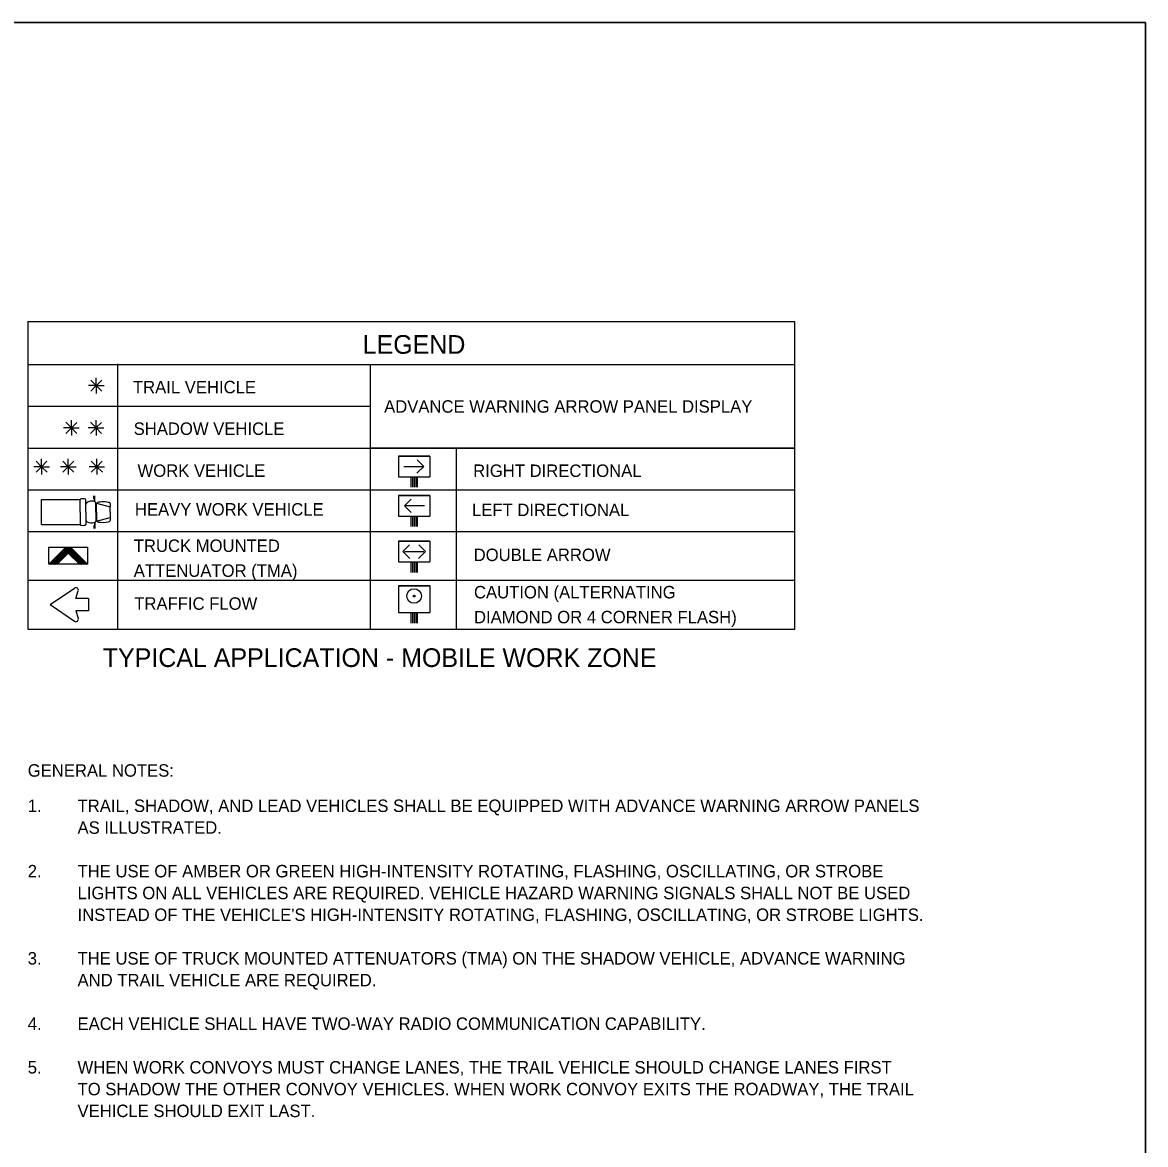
# Model space of a CAD drawing. Extents: x 1374027 to 1374537, y 380415 to 381405.
# Drawn here: x 1374143 to 1374197.1, y 381351.1 to 381405.2 of the extents above; entities that cross this region are included whole.
import ezdxf

# ---------------------------------------------------------------- set-up
doc = ezdxf.new("R2010")
doc.units = 0
doc.layers.add('DSN_DRFT_Junk-No-Plot', color=7, linetype='Continuous')
doc.layers.add('Working Level 1', color=7, linetype='Continuous')

msp = doc.modelspace()

# ---------------------------------------------------------------- linework, layer by layer
at = {"layer": 'DSN_DRFT_Junk-No-Plot'}
for points in [[(1374027.083, 381405.174), (1374197.083, 381405.174), (1374197.083, 381295.174), (1374027.083, 381295.174)], [(1374027.083, 381405.174), (1374027.083, 381295.174), (1374197.083, 381295.174), (1374197.083, 381405.174)]]:
    msp.add_lwpolyline(points, close=True, dxfattribs=at)
at = {"layer": 'Working Level 1'}
for p, q in [((1374143.22, 381390.771), (1374143.22, 381375.949)), ((1374143.22, 381390.771), (1374180.187, 381390.771)), ((1374180.187, 381375.949), (1374180.187, 381390.771)), ((1374143.22, 381388.69), (1374180.187, 381388.69)), ((1374147.548, 381388.725), (1374147.548, 381375.949)), ((1374147.548, 381388.725), (1374147.548, 381375.949)), ((1374159.725, 381388.69), (1374159.725, 381375.949)), ((1374146.527, 381387.675), (1374146.261, 381387.941)), ((1374146.52, 381387.67), (1374146.787, 381387.936)), ((1374146.527, 381387.675), (1374146.527, 381388.052)), ((1374146.527, 381387.675), (1374146.15, 381387.675)), ((1374146.527, 381387.675), (1374146.261, 381387.409)), ((1374146.527, 381387.675), (1374146.793, 381387.409)), ((1374146.527, 381387.675), (1374146.527, 381387.299)), ((1374146.527, 381387.675), (1374146.903, 381387.675)), ((1374143.22, 381386.679), (1374159.725, 381386.679)), ((1374145.329, 381385.642), (1374144.953, 381385.643)), ((1374145.329, 381385.642), (1374145.063, 381385.908)), ((1374145.329, 381385.642), (1374145.063, 381385.376)), ((1374145.323, 381385.637), (1374145.59, 381385.903)), ((1374145.329, 381385.642), (1374145.329, 381386.019)), ((1374145.329, 381385.642), (1374145.595, 381385.376)), ((1374145.329, 381385.642), (1374145.329, 381385.266)), ((1374145.329, 381385.642), (1374145.705, 381385.642)), ((1374146.512, 381385.642), (1374146.136, 381385.642)), ((1374146.512, 381385.642), (1374146.246, 381385.908)), ((1374146.512, 381385.642), (1374146.246, 381385.376)), ((1374146.507, 381385.637), (1374146.773, 381385.903)), ((1374146.512, 381385.642), (1374146.512, 381386.019)), ((1374146.512, 381385.642), (1374146.778, 381385.376)), ((1374146.512, 381385.642), (1374146.512, 381385.266)), ((1374146.512, 381385.642), (1374146.888, 381385.642)), ((1374143.22, 381384.668), (1374180.187, 381384.668)), ((1374180.187, 381384.668), (1374159.725, 381384.668)), ((1374163.861, 381384.668), (1374163.861, 381375.948)), ((1374143.888, 381383.769), (1374143.622, 381384.035)), ((1374143.883, 381383.763), (1374144.149, 381384.029)), ((1374143.888, 381383.769), (1374143.888, 381384.145)), ((1374145.178, 381383.769), (1374144.911, 381384.035)), ((1374145.172, 381383.763), (1374145.438, 381384.029)), ((1374145.178, 381383.769), (1374145.178, 381384.145)), ((1374146.551, 381383.769), (1374146.285, 381384.035)), ((1374146.546, 381383.763), (1374146.812, 381384.029)), ((1374146.551, 381383.769), (1374146.551, 381384.145)), ((1374161.088, 381384.279), (1374161.088, 381383.284)), ((1374162.593, 381384.279), (1374161.088, 381384.279)), ((1374161.088, 381384.279), (1374162.592, 381384.279)), ((1374162.305, 381383.782), (1374161.986, 381384.101)), ((1374162.593, 381384.279), (1374162.593, 381383.284)), ((1374143.888, 381383.769), (1374143.512, 381383.769)), ((1374143.888, 381383.769), (1374143.622, 381383.503)), ((1374143.888, 381383.769), (1374144.154, 381383.503)), ((1374143.888, 381383.769), (1374143.888, 381383.392)), ((1374143.888, 381383.769), (1374144.265, 381383.769)), ((1374145.178, 381383.769), (1374144.801, 381383.769)), ((1374145.178, 381383.769), (1374144.911, 381383.503)), ((1374145.178, 381383.769), (1374145.443, 381383.503)), ((1374145.178, 381383.769), (1374145.178, 381383.392)), ((1374145.178, 381383.769), (1374145.554, 381383.769)), ((1374146.551, 381383.769), (1374146.175, 381383.769)), ((1374146.551, 381383.769), (1374146.285, 381383.503)), ((1374146.551, 381383.769), (1374146.818, 381383.503)), ((1374146.551, 381383.769), (1374146.551, 381383.392)), ((1374146.551, 381383.769), (1374146.927, 381383.769)), ((1374161.342, 381383.782), (1374162.305, 381383.782)), ((1374162.305, 381383.782), (1374161.978, 381383.454)), ((1374161.088, 381383.284), (1374162.593, 381383.284)), ((1374161.689, 381383.284), (1374161.689, 381382.777)), ((1374161.764, 381383.284), (1374161.764, 381382.777)), ((1374161.84, 381383.284), (1374161.84, 381382.777)), ((1374161.915, 381383.284), (1374161.915, 381382.777)), ((1374161.991, 381383.284), (1374161.991, 381382.777)), ((1374143.22, 381382.658), (1374180.187, 381382.658)), ((1374143.22, 381382.658), (1374159.717, 381382.658)), ((1374143.888, 381382.182), (1374145.743, 381382.182)), ((1374143.888, 381380.982), (1374143.888, 381382.182)), ((1374145.743, 381381.582), (1374145.743, 381382.182)), ((1374146.027, 381381.582), (1374146.027, 381382.182)), ((1374146.41, 381382.217), (1374146.41, 381382.363)), ((1374146.434, 381382.076), (1374146.434, 381382.363)), ((1374146.453, 381382.076), (1374146.453, 381382.363)), ((1374146.504, 381381.582), (1374146.504, 381382.013)), ((1374146.543, 381382.013), (1374147.192, 381381.837)), ((1374146.543, 381381.582), (1374146.543, 381382.013)), ((1374161.088, 381382.385), (1374161.088, 381381.39)), ((1374162.593, 381382.385), (1374161.088, 381382.385)), ((1374161.088, 381382.385), (1374162.592, 381382.385)), ((1374161.374, 381381.888), (1374161.694, 381382.207)), ((1374162.337, 381381.888), (1374161.374, 381381.888)), ((1374161.374, 381381.888), (1374161.702, 381381.56)), ((1374162.593, 381382.385), (1374162.593, 381381.39)), ((1374145.743, 381381.582), (1374145.743, 381380.982)), ((1374146.027, 381381.582), (1374146.027, 381380.982)), ((1374146.504, 381381.582), (1374146.504, 381381.15)), ((1374146.543, 381381.582), (1374146.543, 381381.15)), ((1374146.543, 381381.15), (1374147.192, 381381.327)), ((1374147.192, 381381.582), (1374147.192, 381381.837)), ((1374147.192, 381381.582), (1374147.192, 381381.327)), ((1374161.088, 381381.39), (1374162.593, 381381.39)), ((1374161.689, 381381.39), (1374161.689, 381380.883)), ((1374161.764, 381381.39), (1374161.764, 381380.883)), ((1374161.84, 381381.39), (1374161.84, 381380.883)), ((1374161.915, 381381.39), (1374161.915, 381380.883)), ((1374161.991, 381381.39), (1374161.991, 381380.883)), ((1374143.888, 381380.982), (1374145.743, 381380.982)), ((1374146.41, 381380.947), (1374146.41, 381380.799)), ((1374146.434, 381381.087), (1374146.434, 381380.799)), ((1374146.453, 381381.087), (1374146.453, 381380.799)), ((1374143.22, 381380.647), (1374180.187, 381380.647)), ((1374144.239, 381379.074), (1374145.05, 381379.886)), ((1374146.102, 381379.08), (1374145.299, 381379.882)), ((1374161.088, 381380.176), (1374161.088, 381379.181)), ((1374162.593, 381380.176), (1374161.088, 381380.176)), ((1374161.088, 381380.176), (1374162.592, 381380.176)), ((1374161.299, 381379.679), (1374161.619, 381379.998)), ((1374162.381, 381379.679), (1374162.061, 381379.998)), ((1374162.593, 381380.176), (1374162.593, 381379.181)), ((1374144.645, 381379.074), (1374145.177, 381379.61)), ((1374145.712, 381379.074), (1374145.177, 381379.61)), ((1374161.088, 381379.181), (1374162.593, 381379.181)), ((1374161.299, 381379.679), (1374161.626, 381379.351)), ((1374161.374, 381379.679), (1374162.305, 381379.679)), ((1374161.689, 381379.181), (1374161.689, 381378.675)), ((1374161.764, 381379.181), (1374161.764, 381378.675)), ((1374161.84, 381379.181), (1374161.84, 381378.675)), ((1374161.915, 381379.181), (1374161.915, 381378.675)), ((1374161.991, 381379.181), (1374161.991, 381378.675)), ((1374162.381, 381379.679), (1374162.053, 381379.351)), ((1374143.22, 381378.31), (1374180.187, 381378.31)), ((1374144.307, 381377.123), (1374145.47, 381377.92)), ((1374145.543, 381377.427), (1374145.657, 381377.781)), ((1374161.088, 381378.036), (1374161.088, 381376.741)), ((1374162.593, 381378.036), (1374161.088, 381378.036)), ((1374161.088, 381378.036), (1374162.592, 381378.036)), ((1374162.593, 381378.036), (1374162.593, 381376.741)), ((1374144.307, 381377.123), (1374145.47, 381376.325)), ((1374146.15, 381377.427), (1374145.543, 381377.427)), ((1374146.15, 381377.427), (1374146.15, 381376.818)), ((1374146.15, 381376.818), (1374145.543, 381376.818)), ((1374145.543, 381376.818), (1374145.657, 381376.465)), ((1374161.088, 381376.741), (1374162.593, 381376.741)), ((1374161.689, 381376.741), (1374161.689, 381376.234)), ((1374161.764, 381376.741), (1374161.764, 381376.234)), ((1374161.84, 381376.741), (1374161.84, 381376.234)), ((1374161.915, 381376.741), (1374161.915, 381376.234)), ((1374161.991, 381376.741), (1374161.991, 381376.234)), ((1374143.22, 381375.949), (1374180.187, 381375.949))]:
    msp.add_line(p, q, dxfattribs=at)
msp.add_lwpolyline([(1374146.102, 381379.889), (1374146.102, 381379.074), (1374144.239, 381379.074), (1374144.239, 381379.889)], close=True, dxfattribs=at)
for points in [[(1374144.28, 381379.116), (1374145.411, 381379.769)], [(1374144.38, 381379.216), (1374145.385, 381379.796)], [(1374144.48, 381379.316), (1374145.358, 381379.823)], [(1374144.581, 381379.416), (1374145.331, 381379.85)], [(1374144.681, 381379.517), (1374145.304, 381379.877)], [(1374144.781, 381379.617), (1374145.242, 381379.883)], [(1374144.881, 381379.717), (1374145.17, 381379.884)], [(1374144.98, 381379.817), (1374145.1, 381379.885)], [(1374145.189, 381379.598), (1374145.438, 381379.742)], [(1374145.216, 381379.571), (1374145.465, 381379.715)], [(1374144.283, 381379.074), (1374145.136, 381379.567)], [(1374144.356, 381379.074), (1374145.041, 381379.47)], [(1374144.429, 381379.074), (1374144.946, 381379.372)], [(1374144.503, 381379.074), (1374144.85, 381379.275)], [(1374144.577, 381379.074), (1374144.754, 381379.177)], [(1374145.243, 381379.545), (1374145.492, 381379.688)], [(1374145.27, 381379.517), (1374145.519, 381379.661)], [(1374145.297, 381379.49), (1374145.546, 381379.634)], [(1374145.324, 381379.463), (1374145.573, 381379.607)], [(1374145.35, 381379.437), (1374145.599, 381379.58)], [(1374145.377, 381379.41), (1374145.626, 381379.554)], [(1374145.404, 381379.383), (1374145.652, 381379.526)], [(1374145.431, 381379.356), (1374145.68, 381379.5)], [(1374145.458, 381379.329), (1374145.706, 381379.473)], [(1374145.485, 381379.302), (1374145.733, 381379.446)], [(1374145.512, 381379.275), (1374145.76, 381379.419)], [(1374145.538, 381379.248), (1374145.787, 381379.391)], [(1374145.565, 381379.222), (1374145.814, 381379.365)], [(1374145.592, 381379.195), (1374145.84, 381379.338)], [(1374145.619, 381379.168), (1374145.867, 381379.311)], [(1374145.646, 381379.14), (1374145.894, 381379.284)], [(1374145.672, 381379.114), (1374145.921, 381379.257)], [(1374145.7, 381379.087), (1374145.947, 381379.23)], [(1374145.751, 381379.074), (1374145.975, 381379.203)], [(1374145.825, 381379.074), (1374146.001, 381379.177)], [(1374145.899, 381379.074), (1374146.028, 381379.149)], [(1374144.65, 381379.074), (1374144.658, 381379.08)], [(1374145.972, 381379.074), (1374146.055, 381379.122)], [(1374146.046, 381379.074), (1374146.081, 381379.095)]]:
    msp.add_lwpolyline(points, dxfattribs=at)
for radius in [0.351, 0.0437]:
    msp.add_circle((1374161.84, 381377.538), radius, dxfattribs=at)
for centre, radius, start, end in [((1374147.033, 381381.921), 0.18, 331.8801, 28.1199), ((1374147.033, 381381.242), 0.18, 331.8801, 28.1199), ((1374145.54, 381377.819), 0.123, 342.1824, 124.4455), ((1374145.54, 381376.426), 0.123, 235.5546, 17.8176)]:
    msp.add_arc(centre, radius, start, end, dxfattribs=at)
for centre, major_axis, ratio, start_param, end_param in [((1374145.885, 381382.181), (0.142, 0), 0.269913, 0, 3.141593), ((1374146.266, 381381.984), (0.238, 0.029), 0.503092, 0, 3.141593), ((1374146.868, 381382.009), (0.324, -0.004), 0.2034, 0, 3.141593), ((1374145.885, 381380.982), (0.142, 0), 0.269913, 3.141593, 6.283185), ((1374146.266, 381381.179), (0.238, -0.029), 0.503092, 3.141593, 6.283185), ((1374146.868, 381381.154), (0.324, 0.004), 0.2034, 3.141593, 6.283185)]:
    msp.add_ellipse(centre, major_axis=major_axis, ratio=ratio, start_param=start_param, end_param=end_param, dxfattribs=at)

# ---------------------------------------------------------------- texts
for s, height, p in [('LEGEND', 0.9, (1374159.362, 381389.21)), ('TRAIL VEHICLE', 0.6, (1374148.291, 381387.306)), ('ADVANCE WARNING ARROW PANEL DISPLAY', 0.6, (1374160.394, 381386.372)), ('SHADOW VEHICLE', 0.6, (1374148.326, 381385.302)), ('WORK VEHICLE', 0.6, (1374148.513, 381383.28)), ('RIGHT DIRECTIONAL', 0.6, (1374164.685, 381383.276)), ('HEAVY WORK VEHICLE', 0.6, (1374148.386, 381381.415)), ('LEFT DIRECTIONAL', 0.6, (1374164.63, 381381.387)), ('TRUCK MOUNTED ', 0.6, (1374148.33, 381379.663)), ('DOUBLE ARROW', 0.6, (1374164.709, 381379.223)), ('ATTENUATOR (TMA)', 0.6, (1374148.33, 381378.463)), ('CAUTION (ALTERNATING ', 0.6, (1374164.724, 381377.425)), ('TRAFFIC FLOW', 0.6, (1374148.356, 381376.876)), ('DIAMOND OR 4 CORNER FLASH)', 0.6, (1374164.724, 381376.225)), ('TYPICAL APPLICATION - MOBILE WORK ZONE', 0.9, (1374146.836, 381374.12)), ('GENERAL NOTES:', 0.6, (1374143.222, 381368.834)), ('1. ', 0.6, (1374143.222, 381367.133)), ('TRAIL, SHADOW, AND LEAD VEHICLES SHALL BE EQUIPPED WITH ADVANCE WARNING ARROW PANELS', 0.6, (1374145.622, 381367.133)), ('AS ILLUSTRATED. ', 0.6, (1374145.622, 381366.083)), ('2.', 0.6, (1374143.222, 381363.983)), ('THE USE OF AMBER OR GREEN HIGH-INTENSITY ROTATING, FLASHING, OSCILLATING, OR STROBE ', 0.6, (1374145.622, 381363.983)), ('LIGHTS ON ALL VEHICLES ARE REQUIRED. VEHICLE HAZARD WARNING SIGNALS SHALL NOT BE USED ', 0.6, (1374145.622, 381362.933)), ("INSTEAD OF THE VEHICLE'S HIGH-INTENSITY ROTATING, FLASHING, OSCILLATING, OR STROBE LIGHTS.", 0.6, (1374145.622, 381361.883)), ('3. ', 0.6, (1374143.222, 381359.783)), ('THE USE OF TRUCK MOUNTED ATTENUATORS (TMA) ON THE SHADOW VEHICLE, ADVANCE WARNING', 0.6, (1374145.622, 381359.783)), ('AND TRAIL VEHICLE ARE REQUIRED.', 0.6, (1374145.622, 381358.733)), ('4. ', 0.6, (1374143.222, 381356.633)), ('EACH VEHICLE SHALL HAVE TWO-WAY RADIO COMMUNICATION CAPABILITY. ', 0.6, (1374145.622, 381356.633)), ('5. ', 0.6, (1374143.222, 381354.533)), ('WHEN WORK CONVOYS MUST CHANGE LANES, THE TRAIL VEHICLE SHOULD CHANGE LANES FIRST ', 0.6, (1374145.622, 381354.533)), ('TO SHADOW THE OTHER CONVOY VEHICLES. WHEN WORK CONVOY EXITS THE ROADWAY, THE TRAIL', 0.6, (1374145.622, 381353.483)), ('VEHICLE SHOULD EXIT LAST.', 0.6, (1374145.622, 381352.433))]:
    msp.add_text(s, height=height, dxfattribs=at).set_placement(p)

doc.saveas('drawing.dxf')
